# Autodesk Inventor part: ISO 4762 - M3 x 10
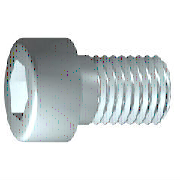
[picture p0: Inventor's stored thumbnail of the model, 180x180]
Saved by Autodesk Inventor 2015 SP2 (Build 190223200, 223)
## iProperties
IsCustomPart: 0
Created: 2012-02
Part Number: ISO 4762 - M3 x 10
Material: Edelstahl, 440C
Description: Innensechskantschraube
Document SubType Name: Modeling
Standard: ISO 4762
Designer: Ente
Standard Revision: 1998
Standards Organization: DIN
Language: de-DE
Size Designation: M3 x 10
Categories: <MemberInstance><Categories><Category DisplayName="Verbindungselemente" InternalName="e4da775c-781d-43d5-af7c-5136215cf5a6" Mnemonic="FSTN"><Category DisplayNam
Density: 7.75 g/cm^3
Appearance: Halbpoliert
Author: Ente
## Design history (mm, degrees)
sketch "Skizze1"
  geometry: L1 (-0.867, 0)-(10, 0); L2 (10, 0)-(10, 1.5); L3 (10, 1.5)-(1.25, 1.5); L4 (1.25, 1.5)-(0.943, 1.5); L5 (0.943, 1.5)-(0, 1.5); L6 (0, 1.5)-(0, 2.75); L7 (0, 2.75)-(-3, 2.75); L8 (-3, 2.75)-(-3, 1.443); L9 (-3, 1.443)-(-1.7, 1.443); L10 (-1.7, 1.443)-(-0.867, 0); L11 (-5.6, 0)-(12.6, 0) reference; L12 (0, -0.55)-(0, 3.3) reference; L13 (1.25, 1.5)-(0, 1.5)
  constraints: 22 end point, 6 parallel, 2 collinear, 2 perpendicular, 1 horizontal, 1 point on line
  dimensions: "d1" = 8.75 distance from line of L3.end L2 (= GEL); "d2" = 0.30683 distance of L4.end L3.end (computed from GAL); "d3" = 3 distance between parallel lines of L8 L6 (= KOH); "d4" = 1.3 distance of L8.end L9.end (= INTI); "d5" = 60 deg angle of L10 L1; "d6" = 3 diameter of L3 L1 (= GD); "d7" = 3 diameter of L5 L1 (= BDM); "d8" = 2.88675 diameter of L9 L1 (= 1.1547 x SW); "d9" = 5.5 diameter of L7 L1 (= KOD); "d26" = 10 distance between parallel lines of L12 L2 (= NLG)
revolve "Körper" sketch "Skizze1" stored, may be unused: angle "d10" = 90 deg
sketch "Skizze2"
  geometry: L1 (0, -3.85)-(0, 3.85) reference; L2 (-3.85, 0)-(3.85, 0) reference; L3 (1.443, 0)-(0.722, -1.25); L4 (0.722, -1.25)-(-0.722, -1.25); L5 (-0.722, -1.25)-(-1.443, 0); L6 (-1.443, 0)-(-0.722, 1.25); L7 (-0.722, 1.25)-(0.722, 1.25); L8 (0.722, 1.25)-(1.443, 0); 2 further points
  constraints: 12 end point, 1 coincident, 1 horizontal alignment, 1 point on line, 12 other
extrude "Loch" join sketch "Skizze2" stored distance "d11" = 10; taper "d12" = 0 deg
workplane "Work Plane1"
fillet "Fillet2" dims "d30" = 0.1 (= R)
body "Solid1"
fillet "Rundung1" dims "d17" = 0.3 (= RR)
feature "Gewinde" dims "d13" = 8.75 (= GEL), "d14" = 0
chamfer "Fase1" distance "d15" = 0.30673 (= -0.5 x SPD + 0.5 x GD); stored, may be unused: second distance "d16" = 0.30673 (= GUL), angle "d27" = 45 deg
other parameters: "GD" = 3 [user parameter; used in 2 equation terms], "NLG" = 10 [user parameter; used in 1 equation term], "GEL" = 8.75 [user parameter; used in 2 equation terms], "KOD" = 5.5 [user parameter; used in 1 equation term], "KOH" = 3 [user parameter; used in 1 equation term], "INTI" = 1.3 [user parameter; used in 1 equation term], "GAL" = 0.30673 (= 0.61345 x PTC) [user parameter; used in 1 equation term], "GUL" = 0.30673 (= 0.61345 x PTC) [user parameter; used in 1 equation term], "BDM" = 3 (= NND) [user parameter; used in 1 equation term], "SW" = 2.5 [user parameter; used in 2 equation terms], "RR" = 0.3 [user parameter; used in 1 equation term], "SPD" = 2.38655 (= NND - 1.2269 x PTC) [user parameter; used in 1 equation term], "d19" = 0, "d28" = 0, "d29" = 0, "R" = 0.1 [user parameter; used in 1 equation term], "TOA" = 30 deg [user parameter], "GD1" = 2.38655 (= THREADDIA - 1.2269 x PTC) [user parameter], "THREADDIA" = 3 [user parameter; used in 1 equation term], "FAWI" = 45 deg [user parameter], "PTC" = 0.5 [user parameter; used in 5 equation terms], "NND" = 3 [user parameter; used in 2 equation terms], "E0" = 2.8875 (= 1.155 x SW) [user parameter]
